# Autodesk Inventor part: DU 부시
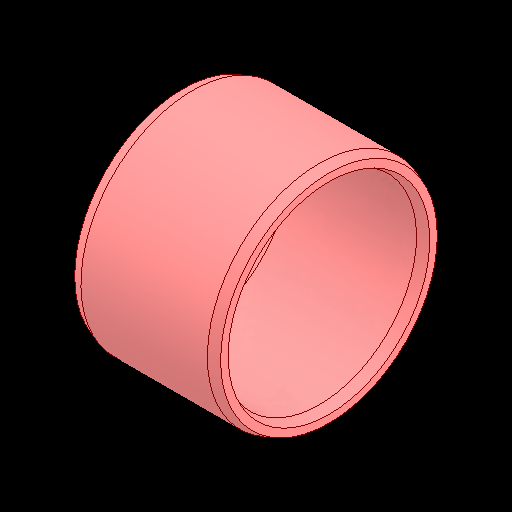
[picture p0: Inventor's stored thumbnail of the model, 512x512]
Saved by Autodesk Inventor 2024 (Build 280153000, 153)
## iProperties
Created: 2025-10
Part Number: DU 부시
Material: 스테인리스스틸
Document SubType Name: Modeling
Designer: EDU03
Density: 8 g/cm^3
Appearance: 기본값
Author: jhkim
Sending System: Autodesk Inventor 2026
Preprocessor: ST-DEVELOPER v20.1
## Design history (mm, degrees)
node "DU 부시1"
node "솔리드2"
node "솔리드1"
